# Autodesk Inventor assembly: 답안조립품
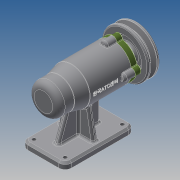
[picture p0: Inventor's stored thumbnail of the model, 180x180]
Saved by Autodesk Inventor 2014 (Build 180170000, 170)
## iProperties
Created: 2019-07
Part Number: 답안조립품
Document SubType Name: Assembly
Designer: kb541-07
Author: kb541-07
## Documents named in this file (12)
- C:\Users\kb541-07\Desktop\490704V1077\답안조립품.iam
- C:\Users\kb541-07\Desktop\490704V1077\본체.ipt
- C:\Users\kb541-07\Desktop\490704V1077\V벨트풀리.ipt
- C:\Users\kb541-07\Desktop\490704V1077\멈춤나사 M3.ipt
- C:\Users\kb541-07\Desktop\490704V1077\베어링 6004.ipt
- C:\Users\kb541-07\Desktop\490704V1077\베어링 51202.ipt
- C:\Users\kb541-07\Desktop\490704V1077\볼트 M4.ipt
- C:\Users\kb541-07\Desktop\490704V1077\어댑터슬리브.ipt
- C:\Users\kb541-07\Desktop\490704V1077\오일 실.ipt
- C:\Users\kb541-07\Desktop\490704V1077\축.ipt
- C:\Users\kb541-07\Desktop\490704V1077\커버.ipt
- C:\Users\kb541-07\Desktop\490704V1077\키 5 x 5 x 16.ipt
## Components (1 placed, 1 different names)
1. V벨트풀리:1
